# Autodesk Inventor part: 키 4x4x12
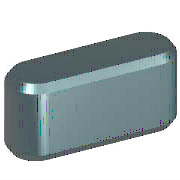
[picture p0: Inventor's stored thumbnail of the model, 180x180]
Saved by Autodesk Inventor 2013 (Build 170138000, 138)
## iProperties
Created: 2012-02
Part Number: 키 4x4x12
Material: 강철, 연강
Description: 키 및 해당 키홈
Document SubType Name: Modeling
Standard: KS B 1311
Designer: mduedu
Standards Organization: KS
Language: ko-KR
Size Designation: 4 x 4 x 12
Categories: <MemberInstance><Categories><Category DisplayName="샤프트 부품" InternalName="7f7aeb1f-a693-4053-b835-cee3144e0d98" Mnemonic="SHFT"><Category DisplayName="키" Interna
Density: 1 g/cm^3
IsCustomPart: 1
Author: mduedu
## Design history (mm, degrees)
workplane "Work Plane1"
workplane "Work Plane2"
sketch "스케치1"
  geometry: L1 (2, 2)-(10, 2); L2 (10, -2)-(2, -2); L3 (0, 9.4)-(0, -7.4) reference; L4 (-5, 0)-(30, 0) reference; L5 (12, 0)-(12, 7); A1 r 2 centre (2, 0) between (2, 2) and (2, -2); A2 r 2 centre (10, 0) between (10, -2) and (10, 2)
  constraints: 6 end point, 5 point on circle, 4 tangent, 3 point on line, 2 centre point, 1 horizontal, 1 parallel, 1 perpendicular
  dimensions: "d0" = 2 radius of A1 (= 0.5 x PB); "d13" = 2 radius of A2 (= 0.5 x PB); "d14" = 12 distance between parallel lines of L5 L3 (= NLG)
extrude "본체1" new body sketch "스케치1" taper "d3" = 0 deg; stored distance "d4" = 10
workplane "Work Plane3"
body "Solid1"
chamfer "모따기1" distance "d8" = 0.25 (= PHH); stored, may be unused: second distance "d9" = 0.25 (= PHH), angle "d15" = 45 deg
other parameters: "d1" = -2.5 (= -PNT), "d2" = 1.5 (= PH - PNT), "NLG" = 12 [user parameter; used in 3 equation terms], "PB" = 4 [user parameter; used in 2 equation terms], "PNT" = 2.5 [user parameter; used in 2 equation terms], "PH" = 4 [user parameter; used in 1 equation term], "PHH" = 0.25 [user parameter; used in 2 equation terms], "d10" = 0, "d16" = 0, "d17" = 0, "d18" = 0, "PLB2" = 12 (= NLG) [user parameter], "WDMAX" = 12 [user parameter], "PLB1" = 12 (= NLG) [user parameter], "RR" = 0.08 [user parameter], "PUEB" = 1.8 [user parameter]
